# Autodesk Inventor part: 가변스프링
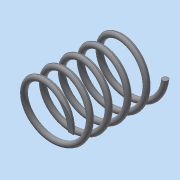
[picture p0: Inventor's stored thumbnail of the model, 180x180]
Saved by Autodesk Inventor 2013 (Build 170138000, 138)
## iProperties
Created: 2017-01
Part Number: 가변스프링
Material: 일반
Document SubType Name: Modeling
Designer: dgall
Density: 1 g/cm^3
Author: dgall
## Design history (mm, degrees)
sketch "스케치1"
  geometry: L1 (20, 0)-(0, 0); L2 (0, 0)-(0, 67.25); L3 (0, 67.25)-(20, 67.25); C1 r 2 at (20, 0); 1 further point
  constraints: 6 end point, 2 coincident, 1 centre point, 1 horizontal, 1 parallel, 1 perpendicular, 1 vertical alignment
  dimensions: "d0" = 40 diameter of L1.start L2; "d2" = 67.25001 distance of L1.end L2.end (derived); "d3" = 4 diameter of C1
feature "코일1" sketch "스케치1" pitch "d4" = 10; turns "d6" = 5; dims "d5" = 67.25001 (= d2), "d7" = 0, angle "d8" = 90 deg, angle "d9" = 90 deg, "d10" = 0, "d11" = 0
node "작업 평면2"
  node "작업 평면1"
feature "분할1"
feature "분할2"
node "솔리드1"
other parameters: "d12" = 0
